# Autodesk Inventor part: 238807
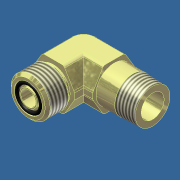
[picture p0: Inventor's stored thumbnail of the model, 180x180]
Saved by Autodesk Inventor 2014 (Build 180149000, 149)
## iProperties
Shininess: 20.0
Length Units: 11272
Angle Units: 11279
Time Units: 11290
Mass Units: 11286
Length Display Precision: 3
Angle Display Precision: 2
Company: Autodesk, Inc.
Created: 2002-05
Part Number: 238807
Material: Stainless Steel 316
Description: FITTING; EL-BC912-(SS)
Document SubType Name: Modeling
Designer: Autodesk, Inc.
Density: 8.182 g/cm^3
Mass: 295.419 g
Surface Area: 130.984 cm^2
Volume: 36.106 cm^3
Appearance: Stainless Steel
Density: 0.0
Volumn: 0.0
Area: 0.0
PropertySet Name: Model Information
Control State: 0
Master: False
Checked Out: True
Last Check In By: JT
Last Check In Date: 2003-06-20
Title: FITTING; EL-BC912-(SS)
Author: Autodesk, Inc.
Comments: -
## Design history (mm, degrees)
derived "EL-BC9.ipt"
body "Solid1"
tag "TaggingFeature2"
feature "Solid1::EL-BC9.ipt" dims "ScaleForDerivedMember" = 10
